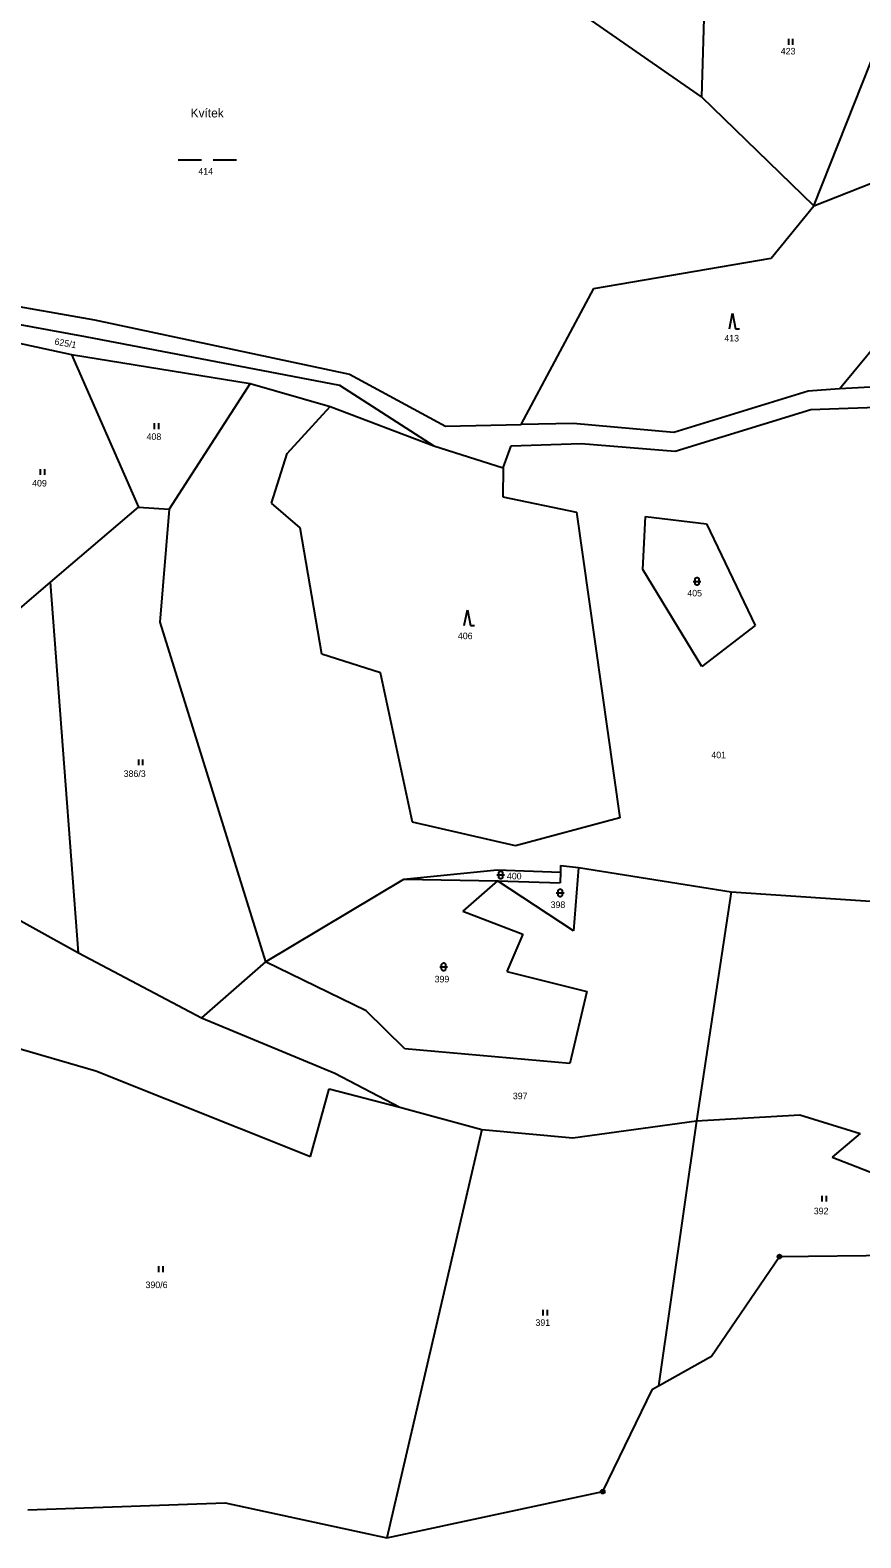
# Model space of a CAD drawing. Extents: x -794421 to -792735, y -1117671 to -1115559.
# Drawn here: x -794032.7 to -793818.1, y -1117493.3 to -1117103.6 of the extents above; entities that cross this region are included whole.
import ezdxf

# ---------------------------------------------------------------- set-up
doc = ezdxf.new("R2010")
doc.units = 0
for name, color, linetype in [('Vrstva 1', 7, 'Continuous'), ('Vrstva 14', 7, 'Continuous'), ('Vrstva 23', 7, 'Continuous'), ('Vrstva 28', 7, 'Continuous'), ('Vrstva 4', 7, 'Continuous'), ('Vrstva 44', 7, 'Continuous')]:
    doc.layers.add(name, color=color, linetype=linetype)

msp = doc.modelspace()

# ---------------------------------------------------------------- linework, layer by layer
at = {"layer": 'Vrstva 1'}
for p, q in [((-793830.24, -1117149), (-793803.5, -1117081.51)), ((-793858.18, -1117084.24), (-793859.21, -1117120.82)), ((-793859.21, -1117120.82), (-793890.76, -1117098.96)), ((-793830.24, -1117149), (-793859.21, -1117120.82)), ((-793830.24, -1117149), (-793815.11, -1117143.08)), ((-793841.21, -1117162.54), (-793830.24, -1117149)), ((-793887.01, -1117170.4), (-793841.21, -1117162.54)), ((-794064.52, -1117169.88), (-794016.07, -1117178.47)), ((-793905.84, -1117205.57), (-793887.01, -1117170.4)), ((-793823.59, -1117196.32), (-793802.76, -1117171.03)), ((-794069.63, -1117173.34), (-794018.51, -1117182.79)), ((-794059.57, -1117179.25), (-794022.04, -1117187.47)), ((-794016.07, -1117178.47), (-793950.14, -1117192.54)), ((-794018.51, -1117182.79), (-793952.74, -1117195.38)), ((-794022.04, -1117187.47), (-793975.81, -1117194.94)), ((-794022.04, -1117187.47), (-794004.73, -1117226.93)), ((-793975.81, -1117194.94), (-793996.75, -1117227.43)), ((-793975.81, -1117194.94), (-793955.18, -1117200.91)), ((-793952.74, -1117195.38), (-793928.4, -1117211.01)), ((-793950.14, -1117192.54), (-793925.42, -1117205.93)), ((-793796.11, -1117194.74), (-793823.59, -1117196.32)), ((-793831.64, -1117196.93), (-793866.41, -1117207.6)), ((-793823.59, -1117196.32), (-793831.64, -1117196.93)), ((-793966.33, -1117213.03), (-793955.18, -1117200.91)), ((-793955.18, -1117200.91), (-793928.4, -1117211.01)), ((-793866.03, -1117212.44), (-793830.98, -1117201.68)), ((-793830.98, -1117201.68), (-793790.72, -1117200.13)), ((-793925.42, -1117205.93), (-793905.84, -1117205.57)), ((-793892.42, -1117205.23), (-793905.84, -1117205.57)), ((-793866.41, -1117207.6), (-793892.42, -1117205.23)), ((-793928.4, -1117211.01), (-793910.45, -1117216.77)), ((-793910.45, -1117216.77), (-793908.44, -1117211.06)), ((-793908.44, -1117211.06), (-793890.34, -1117210.44)), ((-793890.34, -1117210.44), (-793866.03, -1117212.44)), ((-793970.34, -1117225.84), (-793966.33, -1117213.03)), ((-793910.45, -1117216.77), (-793910.57, -1117224.23)), ((-794027.44, -1117246.25), (-794004.73, -1117226.93)), ((-794004.73, -1117226.93), (-793996.75, -1117227.43)), ((-793962.94, -1117232.23), (-793970.34, -1117225.84)), ((-793910.57, -1117224.23), (-793891.53, -1117228.15)), ((-793996.75, -1117227.43), (-793999.17, -1117256.66)), ((-793891.53, -1117228.15), (-793880.32, -1117307.18)), ((-793874.39, -1117243.04), (-793873.68, -1117229.31)), ((-793873.68, -1117229.31), (-793857.97, -1117231.21)), ((-793957.34, -1117264.85), (-793962.94, -1117232.23)), ((-793857.97, -1117231.21), (-793845.38, -1117257.51)), ((-794040.25, -1117257.3), (-794027.44, -1117246.25)), ((-794020.24, -1117342.12), (-794027.44, -1117246.25)), ((-793859.12, -1117268.05), (-793874.39, -1117243.04)), ((-793999.17, -1117256.66), (-793971.9, -1117344.43)), ((-793845.38, -1117257.51), (-793859.12, -1117268.05)), ((-793942.19, -1117269.75), (-793957.34, -1117264.85)), ((-793933.91, -1117308.36), (-793942.19, -1117269.75)), ((-793907.26, -1117314.44), (-793933.91, -1117308.36)), ((-793880.32, -1117307.18), (-793907.26, -1117314.44)), ((-793936.17, -1117323.02), (-793912.04, -1117320.65)), ((-793912.04, -1117320.65), (-793895.69, -1117321.26)), ((-793895.65, -1117319.53), (-793895.69, -1117321.26)), ((-793895.65, -1117319.53), (-793890.98, -1117320)), ((-793890.98, -1117320), (-793892.29, -1117336.38)), ((-793890.98, -1117320), (-793851.54, -1117326.32)), ((-793971.9, -1117344.43), (-793936.17, -1117323.02)), ((-793936.17, -1117323.02), (-793911.93, -1117323.51)), ((-793911.93, -1117323.51), (-793920.89, -1117331.29)), ((-793892.29, -1117336.38), (-793911.93, -1117323.51)), ((-793911.93, -1117323.51), (-793895.76, -1117323.96)), ((-793895.69, -1117321.26), (-793895.76, -1117323.96)), ((-794050.52, -1117325.23), (-794020.24, -1117342.12)), ((-793851.54, -1117326.32), (-793860.52, -1117385.49)), ((-793851.54, -1117326.32), (-793774.25, -1117331.53)), ((-793920.89, -1117331.29), (-793905.37, -1117337.27)), ((-793905.37, -1117337.27), (-793909.53, -1117346.93)), ((-794020.24, -1117342.12), (-793988.41, -1117358.92)), ((-793971.9, -1117344.43), (-793988.41, -1117358.92)), ((-793945.86, -1117357.12), (-793971.9, -1117344.43)), ((-793909.53, -1117346.93), (-793888.85, -1117352.12)), ((-793888.85, -1117352.12), (-793893.24, -1117370.66)), ((-793988.41, -1117358.92), (-793953.93, -1117373.17)), ((-793935.88, -1117366.9), (-793945.86, -1117357.12)), ((-794050.89, -1117362.31), (-794015.76, -1117372.63)), ((-793893.24, -1117370.66), (-793935.88, -1117366.9)), ((-794015.76, -1117372.63), (-793960.26, -1117394.7)), ((-793953.93, -1117373.17), (-793937.21, -1117382)), ((-793960.26, -1117394.7), (-793955.4, -1117377.26)), ((-793955.4, -1117377.26), (-793937.21, -1117382)), ((-793937.21, -1117382), (-793915.98, -1117387.75)), ((-793892.46, -1117389.89), (-793860.52, -1117385.49)), ((-793860.52, -1117385.49), (-793870.36, -1117454)), ((-793860.52, -1117385.49), (-793833.84, -1117384.01)), ((-793833.84, -1117384.01), (-793818.2, -1117388.82)), ((-793915.98, -1117387.75), (-793940.5, -1117493.31)), ((-793915.98, -1117387.75), (-793892.46, -1117389.89)), ((-793818.2, -1117388.82), (-793825.44, -1117394.95)), ((-793825.44, -1117394.95), (-793811.12, -1117400.52))]:
    msp.add_line(p, q, dxfattribs=at)
at = {"layer": 'Vrstva 23'}
for p, q in [((-793836.7, -1117107.35), (-793836.7, -1117105.85)), ((-793835.7, -1117105.85), (-793835.7, -1117107.35)), ((-793994.42, -1117137.15), (-793988.42, -1117137.15)), ((-793985.42, -1117137.15), (-793979.42, -1117137.15)), ((-793852.01, -1117180.77), (-793851.21, -1117176.77)), ((-793851.21, -1117176.77), (-793850.41, -1117180.77)), ((-793850.41, -1117180.77), (-793849.41, -1117180.77)), ((-794000.53, -1117206.72), (-794000.53, -1117205.22)), ((-793999.53, -1117205.22), (-793999.53, -1117206.72)), ((-794030.02, -1117218.53), (-794030.02, -1117217.03)), ((-794029.02, -1117217.03), (-794029.02, -1117218.53)), ((-793861.38, -1117246.09), (-793859.38, -1117246.09)), ((-793860.88, -1117245.49), (-793860.78, -1117245.29)), ((-793860.88, -1117246.69), (-793860.88, -1117245.49)), ((-793860.78, -1117245.29), (-793860.68, -1117245.19)), ((-793860.68, -1117245.19), (-793860.48, -1117245.09)), ((-793860.48, -1117245.09), (-793860.28, -1117245.09)), ((-793860.28, -1117245.09), (-793860.08, -1117245.19)), ((-793860.08, -1117245.19), (-793859.98, -1117245.29)), ((-793859.98, -1117245.29), (-793859.88, -1117245.49)), ((-793859.88, -1117245.49), (-793859.88, -1117246.69)), ((-793860.78, -1117246.89), (-793860.88, -1117246.69)), ((-793860.68, -1117246.99), (-793860.78, -1117246.89)), ((-793860.48, -1117247.09), (-793860.68, -1117246.99)), ((-793860.28, -1117247.09), (-793860.48, -1117247.09)), ((-793860.08, -1117246.99), (-793860.28, -1117247.09)), ((-793859.98, -1117246.89), (-793860.08, -1117246.99)), ((-793859.88, -1117246.69), (-793859.98, -1117246.89)), ((-793920.52, -1117257.44), (-793919.72, -1117253.44)), ((-793919.72, -1117253.44), (-793918.92, -1117257.44)), ((-793918.92, -1117257.44), (-793917.92, -1117257.44)), ((-794004.65, -1117293.58), (-794004.65, -1117292.08)), ((-794003.65, -1117292.08), (-794003.65, -1117293.58)), ((-793912.12, -1117321.96), (-793910.12, -1117321.96)), ((-793911.62, -1117321.36), (-793911.52, -1117321.16)), ((-793911.62, -1117322.56), (-793911.62, -1117321.36)), ((-793911.52, -1117322.76), (-793911.62, -1117322.56)), ((-793911.52, -1117321.16), (-793911.42, -1117321.06)), ((-793911.42, -1117322.86), (-793911.52, -1117322.76)), ((-793911.42, -1117321.06), (-793911.22, -1117320.96)), ((-793911.22, -1117322.96), (-793911.42, -1117322.86)), ((-793911.22, -1117320.96), (-793911.02, -1117320.96)), ((-793911.02, -1117322.96), (-793911.22, -1117322.96)), ((-793911.02, -1117320.96), (-793910.82, -1117321.06)), ((-793910.82, -1117322.86), (-793911.02, -1117322.96)), ((-793910.82, -1117321.06), (-793910.72, -1117321.16)), ((-793910.72, -1117322.76), (-793910.82, -1117322.86)), ((-793910.72, -1117321.16), (-793910.62, -1117321.36)), ((-793910.62, -1117322.56), (-793910.72, -1117322.76)), ((-793910.62, -1117321.36), (-793910.62, -1117322.56)), ((-793896.75, -1117326.59), (-793894.75, -1117326.59)), ((-793896.25, -1117325.99), (-793896.15, -1117325.79)), ((-793896.25, -1117327.19), (-793896.25, -1117325.99)), ((-793896.15, -1117327.39), (-793896.25, -1117327.19)), ((-793896.15, -1117325.79), (-793896.05, -1117325.69)), ((-793896.05, -1117327.49), (-793896.15, -1117327.39)), ((-793896.05, -1117325.69), (-793895.85, -1117325.59)), ((-793895.85, -1117327.59), (-793896.05, -1117327.49)), ((-793895.85, -1117325.59), (-793895.65, -1117325.59)), ((-793895.65, -1117327.59), (-793895.85, -1117327.59)), ((-793895.65, -1117325.59), (-793895.45, -1117325.69)), ((-793895.45, -1117327.49), (-793895.65, -1117327.59)), ((-793895.45, -1117325.69), (-793895.35, -1117325.79)), ((-793895.35, -1117327.39), (-793895.45, -1117327.49)), ((-793895.35, -1117325.79), (-793895.25, -1117325.99)), ((-793895.25, -1117327.19), (-793895.35, -1117327.39)), ((-793895.25, -1117325.99), (-793895.25, -1117327.19)), ((-793926.88, -1117345.72), (-793924.88, -1117345.72)), ((-793926.38, -1117345.12), (-793926.28, -1117344.92)), ((-793926.38, -1117346.32), (-793926.38, -1117345.12)), ((-793926.28, -1117346.52), (-793926.38, -1117346.32)), ((-793926.28, -1117344.92), (-793926.18, -1117344.82)), ((-793926.18, -1117346.62), (-793926.28, -1117346.52)), ((-793926.18, -1117344.82), (-793925.98, -1117344.72)), ((-793925.98, -1117346.72), (-793926.18, -1117346.62)), ((-793925.98, -1117344.72), (-793925.78, -1117344.72)), ((-793925.78, -1117346.72), (-793925.98, -1117346.72)), ((-793925.78, -1117344.72), (-793925.58, -1117344.82)), ((-793925.58, -1117346.62), (-793925.78, -1117346.72)), ((-793925.58, -1117344.82), (-793925.48, -1117344.92)), ((-793925.48, -1117346.52), (-793925.58, -1117346.62)), ((-793925.48, -1117344.92), (-793925.38, -1117345.12)), ((-793925.38, -1117346.32), (-793925.48, -1117346.52)), ((-793925.38, -1117345.12), (-793925.38, -1117346.32)), ((-793828.03, -1117406.38), (-793828.03, -1117404.88)), ((-793827.03, -1117404.88), (-793827.03, -1117406.38)), ((-793999.44, -1117424.62), (-793999.44, -1117423.12)), ((-793998.44, -1117423.12), (-793998.44, -1117424.62)), ((-793900.11, -1117435.84), (-793900.11, -1117434.34)), ((-793899.11, -1117434.34), (-793899.11, -1117435.84))]:
    msp.add_line(p, q, dxfattribs=at)
at = {"layer": 'Vrstva 28'}
for centre, radius in [((-793839.08, -1117420.61), 0.5), ((-793839.08, -1117420.61), 0.01), ((-793884.75, -1117481.37), 0.5), ((-793884.75, -1117481.37), 0.01)]:
    msp.add_circle(centre, radius, dxfattribs=at)
at = {"layer": 'Vrstva 4'}
for p, q in [((-793856.69, -1117446.32), (-793839.08, -1117420.61)), ((-793839.08, -1117420.61), (-793760.68, -1117419.72)), ((-793870.36, -1117454), (-793856.69, -1117446.32)), ((-793884.75, -1117481.37), (-793871.87, -1117454.84)), ((-793871.87, -1117454.84), (-793870.36, -1117454)), ((-794033.25, -1117486.1), (-793982.31, -1117484.24)), ((-793982.31, -1117484.24), (-793940.5, -1117493.31)), ((-793940.5, -1117493.31), (-793884.75, -1117481.37))]:
    msp.add_line(p, q, dxfattribs=at)

# ---------------------------------------------------------------- texts
at = {"layer": 'Vrstva 14'}
for s, p in [('423', (-793838.752, -1117109.88)), ('414', (-793989.232, -1117140.94)), ('413', (-793853.336, -1117184.07)), ('408', (-794002.612, -1117209.52)), ('409', (-794032.182, -1117221.55)), ('405', (-793862.898, -1117249.97)), ('406', (-793922.182, -1117261.02)), ('401', (-793856.685, -1117291.79)), ('386/3', (-794008.53, -1117296.63)), ('400', (-793909.511, -1117323.11)), ('398', (-793898.227, -1117330.51)), ('399', (-793928.187, -1117349.74)), ('397', (-793907.973, -1117379.93)), ('392', (-793830.217, -1117409.67)), ('390/6', (-794002.879, -1117428.76)), ('391', (-793902.13, -1117438.51))]:
    msp.add_text(s, height=1.7, dxfattribs=at).set_placement(p)
msp.add_text('625/1', height=1.7, rotation=349.9335, dxfattribs=at).set_placement((-794026.499, -1117184.856))
at = {"layer": 'Vrstva 44'}
msp.add_text('Kvítek', height=2.3, dxfattribs=at).set_placement((-793991.22, -1117126.15))

doc.saveas('drawing.dxf')
